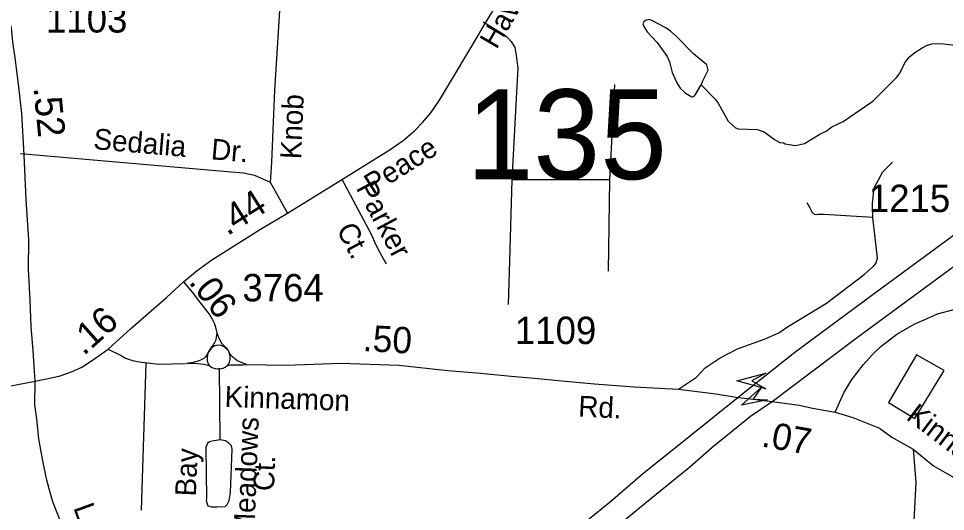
# Model space of a CAD drawing. Extents: x 1547597 to 1699558, y 810033 to 920809.
# Drawn here: x 1589892 to 1594126, y 836281 to 838531 of the extents above; entities that cross this region are included whole.
import ezdxf

# ---------------------------------------------------------------- set-up
doc = ezdxf.new("R2010")
doc.units = 0
for name, color, linetype in [('Exist Cultural Warehouse Building Footprint', 7, 'Continuous'), ('Exist Hydrographic Misc Water Feature', 7, 'Continuous'), ('Exist Road Non-System Type 51', 7, 'Continuous'), ('Exist Road Non-System Type 51 Label', 7, 'Continuous'), ('Exist Road Primary Interstate Divided Center Attributed', 7, 'Continuous'), ('Exist Road Primary Interstate Structure Cantilever Sign Attributed CELL', 7, 'Continuous'), ('Exist Road Secondary Mileage Hundredths English Label', 7, 'Continuous'), ('Exist Road Secondary Structure Standard Bridge Attributed CELL', 7, 'Continuous'), ('Exist Road Secondary Structure Standard Bridge Number Label', 7, 'Continuous'), ('Exist Road Secondary Type 51 Attributed', 7, 'Continuous'), ('Exist Road Secondary Type 51 Divided Attributed', 7, 'Continuous'), ('Exist Road Secondary Type 51 Label', 7, 'Continuous'), ('Exist Road Secondary Type 51 Number Label', 7, 'Continuous'), ('Exist Road Secondary Type 51 Undivided 4 Lane Attributed', 7, 'Continuous')]:
    doc.layers.add(name, color=color, linetype=linetype)

msp = doc.modelspace()

# ---------------------------------------------------------------- linework, layer by layer
at = {"layer": 'Exist Cultural Warehouse Building Footprint'}
msp.add_lwpolyline([(1593993.2, 836995.9), (1593866.3, 836777.9), (1593986.1, 836706), (1594120.1, 836924)], close=True, dxfattribs=at)
at = {"layer": 'Exist Hydrographic Misc Water Feature'}
for points in [[(1593010.5, 838228.2), (1593017.3, 838247.5), (1593041.8, 838295.2), (1593036.2, 838319.2), (1592974.8, 838370), (1592897.7, 838448.9), (1592870, 838473.2), (1592848.3, 838489.5), (1592784.6, 838522.3), (1592770.7, 838526.5), (1592756.6, 838522.6), (1592748.6, 838516.7), (1592744.4, 838506.8), (1592748.3, 838494.7), (1592764, 838470.5), (1592809.4, 838422), (1592854.6, 838357.4), (1592866.4, 838333.3), (1592877.8, 838285.2), (1592899.2, 838237), (1592914.9, 838212.8), (1592938.7, 838190.5), (1592968.4, 838174.1), (1592976.4, 838176), (1592984.5, 838183.9), (1593010.5, 838228.2)], [(1593580.6, 838017.3), (1593607.2, 838036.2), (1593659.5, 838061.4), (1593794.6, 838153.5), (1593902, 838262), (1593914.2, 838277.8), (1593942.9, 838333.4), (1593961.3, 838357.1), (1593985.6, 838376.8), (1594015.7, 838394.4), (1594039.9, 838408), (1594064, 838415.7), (1594104, 838417.2), (1594247.8, 838401.2)], [(1593010.5, 838228.2), (1593074.3, 838162.8), (1593088.1, 838144.6), (1593133.1, 838062.1), (1593166.7, 838031.7), (1593178.7, 838027.5), (1593266.6, 838024.4), (1593298.5, 838014), (1593346, 837978.4), (1593369.8, 837965.9), (1593385.8, 837963.8), (1593393.8, 837958.8), (1593441.7, 837952.1), (1593481.8, 837960.2), (1593552.2, 838002.9), (1593580.6, 838017.3)]]:
    msp.add_lwpolyline(points, dxfattribs=at)
at = {"layer": 'Exist Road Non-System Type 51'}
for p, q in [((1592614.3, 838230.4), (1592591.9, 837794.4)), ((1591041.7, 837784.8), (1591121.1, 837642.7)), ((1592591.9, 837794.4), (1592145.8, 837794.8)), ((1592591.9, 837794.4), (1592585.8, 837378.3)), ((1590453.1, 836286.6), (1590474.7, 836956.8)), ((1590813.8, 836607.5), (1590810.2, 836934.5))]:
    msp.add_line(p, q, dxfattribs=at)
for points in [[(1591103.6, 838910.6), (1591083.3, 838541.5), (1591062, 838203.7), (1591048.2, 837875.2), (1591043.6, 837805.1), (1591041.7, 837784.8)], [(1592014.2, 838516.6), (1592099.3, 838463.9), (1592123.2, 838447.4), (1592142.8, 838427.2), (1592158.5, 838398.9), (1592165.9, 838362.9), (1592173.2, 838304.7), (1592167.5, 838194.8), (1592145.8, 837794.8)], [(1589901, 837914.8), (1590863.6, 837831.4), (1590919.6, 837826.6), (1590969.4, 837815.8), (1591041.7, 837784.8)], [(1593794.5, 837623.5), (1593793.6, 837688.8), (1593800.8, 837758.5), (1593840.1, 837831.7), (1593884.8, 837875.1)], [(1591370.9, 837794.9), (1591503.8, 837544.1), (1591521.2, 837503.7), (1591542.6, 837463.4), (1591560.1, 837429), (1591571.9, 837411)], [(1592145.8, 837794.8), (1592134.5, 837425.4), (1592128.4, 837225)], [(1593794.5, 837623.5), (1593572, 837636.2), (1593560, 837636.3), (1593544, 837636.6), (1593536, 837634.8), (1593528, 837636.7), (1593520.2, 837644.9), (1593516.3, 837651), (1593508.6, 837665.1), (1593494.8, 837689.2)], [(1592907.1, 836838.6), (1592989.1, 836894.3), (1593027.9, 836937), (1593097.5, 836982.8), (1593176, 837023.9), (1593303.3, 837069), (1593365.3, 837096.2), (1593404.1, 837123.4), (1593582.5, 837232.1), (1593755, 837363), (1593797.6, 837400.3), (1593808.5, 837412.8), (1593815.5, 837437.7), (1593794.5, 837623.5)], [(1590301, 837022.1), (1590357.3, 836994.4), (1590381.3, 836981.2), (1590412.4, 836970.4), (1590443.5, 836963.3), (1590481.3, 836959.3), (1590535.1, 836953.4), (1590655.5, 836956.9)], [(1590813.8, 836607.5), (1590775.9, 836602.1), (1590763.8, 836598.3), (1590755.7, 836590.5), (1590747.3, 836574.4), (1590750, 836340.4), (1590749.8, 836330.4), (1590753.7, 836316.3), (1590757.5, 836306.3), (1590773.4, 836301.9), (1590797.4, 836301.6), (1590835.5, 836303.1), (1590845.7, 836313.1), (1590853.9, 836330.9), (1590860.4, 836366.8), (1590867.4, 836564.8), (1590865.5, 836580.8), (1590851.8, 836594.9), (1590838, 836603.2), (1590813.8, 836607.5)], [(1593978.3, 836565.8), (1593990.6, 836413.4), (1593981.7, 836237.9), (1593969.8, 836169.5), (1593937.1, 836095.1), (1593865.7, 836002.9), (1593782.5, 835934.5), (1593720.1, 835898.8), (1593657.7, 835886.9), (1593589.3, 835880.9), (1593512, 835883.9), (1593413.9, 835898.8), (1593306.9, 835937.4), (1593199.9, 835991), (1593095.9, 836056.4), (1592962.1, 836089.2), (1592807.5, 836104), (1592700.5, 836086.2), (1592635.1, 836056.4), (1592430, 835886.9), (1592066.2, 835565.1)]]:
    msp.add_lwpolyline(points, dxfattribs=at)
at = {"layer": 'Exist Road Primary Interstate Divided Center Attributed'}
for points in [[(1596050.3, 838931.7), (1595772.2, 838733.3), (1595438.4, 838484.3), (1595085.3, 838220.8), (1594736, 837957.2), (1594479.2, 837777.2), (1594179.9, 837553.4), (1593789.1, 837267.5), (1593438.8, 837006.5), (1593179.8, 836801.3)], [(1593334.4, 836782.2), (1593718.9, 837071.7), (1594189.7, 837419.1), (1594858.6, 837910.5), (1595328.2, 838256.2), (1595533.3, 838398.8), (1595848.8, 838639.3), (1596089.1, 838817)], [(1591429.3, 835154.1), (1591497.6, 835216.9), (1591601.3, 835313.6), (1591732.1, 835433.5), (1591928.4, 835614.5), (1592120.7, 835787.3), (1592347.1, 835983.3), (1592497.9, 836120.8), (1592610.6, 836200.5), (1592797.1, 836353.9), (1592956.3, 836482.5), (1593058.3, 836572.9), (1593155.5, 836651.2), (1593236.1, 836715.3), (1593334.4, 836782.2)], [(1593179.8, 836801.3), (1592855.5, 836541), (1592742.2, 836450.5), (1592596.4, 836324.6), (1592452.8, 836208.6), (1592308.2, 836073.3), (1592199.1, 835980.8), (1592127.9, 835921.5), (1592033.1, 835831.3), (1591815.6, 835626.2), (1591699.4, 835524.2), (1591621.4, 835450.1), (1591533.6, 835364.8), (1591465.4, 835299)]]:
    msp.add_lwpolyline(points, dxfattribs=at)
at = {"layer": 'Exist Road Primary Interstate Structure Cantilever Sign Attributed CELL'}
msp.add_lwpolyline([(1593305.9, 836841.3), (1593173.4, 836876.8), (1593305.9, 836912.3), (1593242, 836876.8)], close=True, dxfattribs=at)
at = {"layer": 'Exist Road Secondary Structure Standard Bridge Attributed CELL'}
msp.add_lwpolyline([(1593313.2, 836790.8), (1593193.9, 836766), (1593284.8, 836847.2), (1593248.3, 836793.4)], close=True, dxfattribs=at)
at = {"layer": 'Exist Road Secondary Type 51 Attributed'}
for points in [[(1589968.8, 836875.5), (1589959, 837014), (1589949.3, 837125.1), (1589945.4, 837246), (1589937.6, 837386.3), (1589939.6, 837520.9), (1589926.7, 837705.6), (1589917.9, 837909.1), (1589907.4, 838098.3), (1589891.5, 838230.9), (1589877.4, 838352.5), (1589865.7, 838424.6), (1589859.8, 838487), (1589846.2, 838545.5), (1589830.6, 838625.4), (1589817.3, 838692.6), (1589803.4, 838766.9), (1589778, 838875), (1589748.8, 839029), (1589659.4, 839429.4), (1589634.3, 839612.3)], [(1590646, 837329.4), (1590708.5, 837381.2), (1590775.5, 837429.5), (1590893.3, 837504.5), (1590997.8, 837568.9), (1591121.1, 837642.7), (1591352.8, 837786.2), (1591584.7, 837930.4), (1591649.8, 837975.2), (1591701.1, 838018.9), (1591737.4, 838056.7), (1591775.7, 838100.4), (1591815.5, 838158.5), (1591879.4, 838265.3), (1591940.3, 838366.7), (1591992.3, 838453.2), (1592024.1, 838508), (1592089.1, 838615.1)], [(1590301, 837022.1), (1590404, 837113.9), (1590485.7, 837185.8), (1590567.5, 837257.8), (1590646, 837329.4)], [(1590646, 837329.4), (1590685, 837282.7), (1590723.7, 837231.8), (1590752.5, 837195.3), (1590766.1, 837177.3), (1590776.7, 837158.7), (1590787.3, 837136.8), (1590793.3, 837116.9), (1590797.8, 837096.8)], [(1593621.7, 836733.5), (1593661.6, 836822.7), (1593698.1, 836882.9), (1593752, 836951.8), (1593791.3, 836995.8), (1593830.7, 837034.4), (1593903.7, 837089.9), (1593983.6, 837135.7), (1594042.7, 837161.7), (1594089.6, 837183.8), (1594171.2, 837204.6)], [(1589968.8, 836875.5), (1590078.3, 836898), (1590134.7, 836917.7), (1590181.2, 836940.3), (1590230.5, 836971.4), (1590301, 837022.1)], [(1587511.2, 836971.5), (1587660.4, 836943.8), (1587802.9, 836913.2), (1587946.7, 836887.3), (1588124.3, 836854.7), (1588277.7, 836822.3), (1588399.7, 836794.6), (1588667, 836744.6), (1588711.7, 836736.8), (1588794.7, 836728.8), (1588900.4, 836725), (1588993.5, 836735.5), (1589115.1, 836738), (1589234.2, 836747.4), (1589347.3, 836752.9), (1589449.6, 836771.4), (1589517.8, 836782.4), (1589626.2, 836804.8), (1589736.2, 836831.4), (1589968.8, 836875.5)], [(1590931.9, 836951.4), (1591116, 836948), (1591362.8, 836958), (1591629.1, 836948.8), (1591852.6, 836924.3), (1592002.9, 836912.6), (1592142.7, 836898.6), (1592248.7, 836889), (1592356.6, 836879.4), (1592522.4, 836863.1), (1592704.4, 836850.4), (1592907.1, 836838.6)], [(1592907.1, 836838.6), (1593077.3, 836817.4), (1593179.8, 836801.3)], [(1593179.8, 836801.3), (1593248.3, 836793.4), (1593334.4, 836782.2)], [(1593334.4, 836782.2), (1593458.4, 836765.4), (1593519.3, 836752.4), (1593621.7, 836733.5)], [(1593621.7, 836733.5), (1593702.7, 836709.8), (1593824.2, 836660.7), (1593881.1, 836620.4), (1593978.3, 836565.8), (1594070.8, 836489.9), (1594156.2, 836440), (1594227.3, 836378.3), (1594267.6, 836330.8), (1594298.5, 836281), (1594318.3, 836250.2)]]:
    msp.add_lwpolyline(points, dxfattribs=at)
at = {"layer": 'Exist Road Secondary Type 51 Divided Attributed'}
for points in [[(1590797.8, 837096.8), (1590793.2, 837066.1), (1590791.8, 837060.5), (1590788.6, 837053.8), (1590785, 837047.5), (1590782, 837042.8), (1590774.7, 837033.4), (1590771.7, 837029.2), (1590768.3, 837024.1), (1590764.2, 837018.2), (1590762.3, 837014.7), (1590757.9, 837006.3)], [(1590797.8, 837096.8), (1590807.3, 837071.3), (1590815.5, 837055.1), (1590819.1, 837049.7), (1590823.5, 837044.2), (1590840.1, 837027.7), (1590845.8, 837021.2), (1590848.4, 837017.8), (1590851.5, 837013.7)], [(1590851.5, 837013.7), (1590846.3, 837019.5), (1590844.3, 837021.3), (1590841.7, 837023.9), (1590838.3, 837027), (1590832, 837032), (1590829, 837033.9), (1590827.4, 837034.7), (1590824.5, 837035.9), (1590818.2, 837038), (1590812.9, 837038.9), (1590803.7, 837039.5), (1590797, 837039.1), (1590789.1, 837037.3), (1590786.1, 837036.2), (1590782.3, 837034), (1590779.1, 837031.6), (1590775.7, 837028.9), (1590773.8, 837027.1), (1590770.1, 837023.5), (1590767, 837019.2), (1590757.9, 837006.3)], [(1590757.9, 837006.3), (1590751.8, 836995.6), (1590746.3, 836987.3), (1590742.5, 836983.2), (1590738.4, 836979.8), (1590726.8, 836972.4), (1590713.1, 836966.3), (1590689.1, 836960.9), (1590659.6, 836957.1)], [(1590757.9, 837006.3), (1590754.6, 836994.2), (1590753.4, 836986.4), (1590753.5, 836978), (1590754.4, 836968.5), (1590755.3, 836963.9), (1590756.1, 836960.7), (1590757.4, 836957.7), (1590759.1, 836954.3), (1590762, 836950.4), (1590767.2, 836943.8)], [(1590847.7, 836948.5), (1590852.4, 836954.5), (1590855.7, 836962), (1590857.9, 836968.9), (1590859.3, 836975), (1590858.9, 836987.4), (1590857.9, 836994.7), (1590855.5, 837002.7), (1590851.5, 837013.7)], [(1590933.6, 836951.4), (1590906.8, 836962), (1590889.2, 836969.6), (1590879.6, 836977), (1590869.4, 836986.4), (1590864.5, 836991.6), (1590857.4, 837002.7), (1590851.5, 837013.7)], [(1590659.6, 836957.1), (1590695.5, 836958.1), (1590737.9, 836952.6), (1590756.4, 836948.5), (1590761.7, 836946.6), (1590767.2, 836943.8)], [(1590767.2, 836943.8), (1590774.1, 836939.1), (1590776.9, 836937.4), (1590780.2, 836936), (1590790.7, 836933.2), (1590802.3, 836931.9), (1590810.9, 836932.1), (1590818.4, 836933), (1590827.5, 836935.2), (1590836.6, 836939.6), (1590843.6, 836945)], [(1590843.6, 836945), (1590855, 836948.7), (1590861.1, 836949.6), (1590869.8, 836950.8), (1590879.5, 836950.8), (1590889.8, 836950.8), (1590899.5, 836950.5), (1590909.4, 836950.2), (1590916.4, 836950.7), (1590925.9, 836951.1), (1590934, 836951.8)], [(1590843.6, 836945), (1590847.7, 836948.5)]]:
    msp.add_lwpolyline(points, dxfattribs=at)
at = {"layer": 'Exist Road Secondary Type 51 Undivided 4 Lane Attributed'}
msp.add_lwpolyline([(1590460.4, 834740.3), (1590448.5, 834773.1), (1590406.7, 834938), (1590396, 835002.1), (1590383.1, 835089.6), (1590368.8, 835163.2), (1590362.8, 835216.7), (1590353.7, 835285.3), (1590346.8, 835327.9), (1590334.4, 835440), (1590316.2, 835527.4), (1590298.7, 835629.3), (1590274, 835720.1), (1590248, 835810.9), (1590190.8, 835965.4), (1590048.8, 836325.5), (1590037.2, 836367.6), (1590021.5, 836424.3), (1590002.7, 836512.7), (1589985, 836613), (1589975.5, 836703.8), (1589966.8, 836768.3), (1589968.8, 836875.5)], dxfattribs=at)

# ---------------------------------------------------------------- texts
at = {"layer": 'Exist Road Non-System Type 51 Label'}
for s, rotation, p in [('Knob', 87.5266, (1591182.6, 837887.7)), ('Sedalia', 355.0483, (1590231.7, 837935.6)), ('Dr.', 355.0483, (1590768.9, 837889)), ('Parker', 297.9277, (1591431.5, 837758.1)), ('Ct.', 297.9277, (1591342.4, 837568.2)), ('Meadows', 87.7816, (1590968.7, 836167)), ('Bay', 87.7816, (1590702.2, 836348.4)), ('Ct.', 87.7816, (1591058.8, 836372.5))]:
    msp.add_text(s, height=95, rotation=rotation, dxfattribs=at).set_placement(p)
at = {"layer": 'Exist Road Secondary Mileage Hundredths English Label'}
for s, height, rotation, p in [('.52', 125, 275.6154, (1589960.1, 838215.9)), ('.44', 120, 32.2817, (1590846.1, 837537.1)), ('.06', 120, 308.2474, (1590666.1, 837326.8)), ('.16', 120, 41.6996, (1590189.8, 836989)), ('.50', 120, 356.7264, (1591463.2, 837013.7)), ('.07', 120, 349.8688, (1593281.9, 836578.1))]:
    msp.add_text(s, height=height, rotation=rotation, dxfattribs=at).set_placement(p)
at = {"layer": 'Exist Road Secondary Structure Standard Bridge Number Label'}
msp.add_text('135', height=410.1, dxfattribs=at).set_placement((1591938.9, 837797.8))
at = {"layer": 'Exist Road Secondary Type 51 Label'}
for s, rotation, p in [('Haven', 59.7387, (1592075.4, 838387)), ('Peace', 32.216, (1591510, 837725.1)), ('Kinnamon', 358.1198, (1590832.5, 836758.5)), ('Rd.', 357.1379, (1592447.3, 836714.8)), ('Kinnamon', 322.679, (1593942, 836704.5)), ('Lewisville', 289.9215, (1590141.7, 836298.4))]:
    msp.add_text(s, height=95, rotation=rotation, dxfattribs=at).set_placement(p)
at = {"layer": 'Exist Road Secondary Type 51 Number Label'}
for s, p in [('1103', (1590017.6, 838467.3)), ('1215', (1593776.1, 837647.6)), ('3764', (1590914.7, 837240.2)), ('1109', (1592159.5, 837045.1))]:
    msp.add_text(s, height=125, dxfattribs=at).set_placement(p)

doc.saveas('drawing.dxf')
